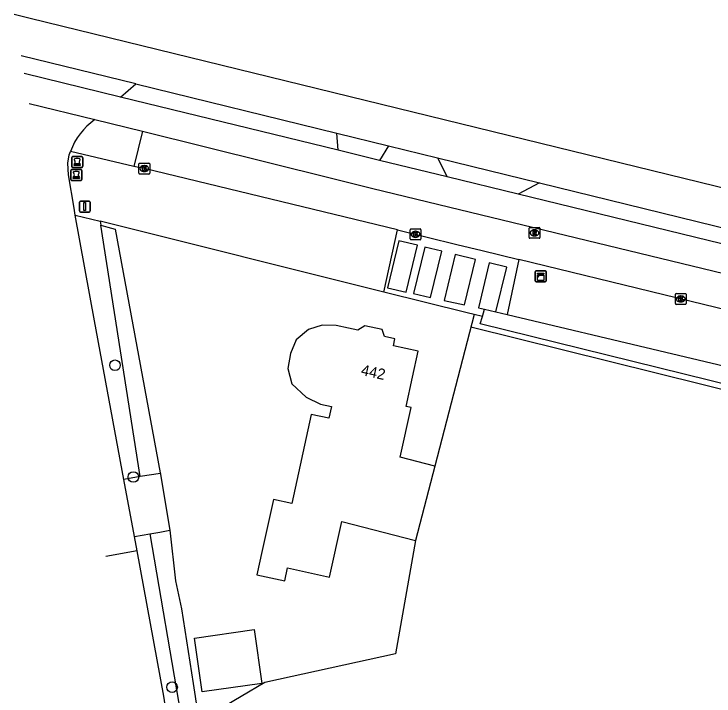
# Model space of a CAD drawing. Extents: x 163863 to 164644, y 379566 to 382155.
# Drawn here: x 164350.9 to 164415.3, y 382091.7 to 382154.5 of the extents above; entities that cross this region are included whole.
import ezdxf

# ---------------------------------------------------------------- set-up
doc = ezdxf.new("R2010")
doc.units = 0
for name, color, linetype in [('IMGEO_Berm_groen', 7, 'Continuous'), ('IMGEO_Bolder', 7, 'Continuous'), ('IMGEO_Boom', 7, 'Continuous'), ('IMGEO_Fietspad_gesloten', 7, 'Continuous'), ('IMGEO_Fietspad_open', 7, 'Continuous'), ('IMGEO_Grasland_agrarisch', 7, 'Continuous'), ('IMGEO_Groenvoorziening', 7, 'Continuous'), ('IMGEO_Hek', 7, 'Continuous'), ('IMGEO_Kast', 7, 'Continuous'), ('IMGEO_Kolk', 7, 'Continuous'), ('IMGEO_Pand', 7, 'Continuous'), ('IMGEO_Pand_nummerreeks', 7, 'Continuous'), ('IMGEO_Parkeervlak_open', 7, 'Continuous'), ('IMGEO_Rijbaan_lokaal_halfverhard', 7, 'Continuous'), ('IMGEO_Rijbaan_lokaal_open', 7, 'Continuous'), ('IMGEO_Rijbaan_regionaal_gesloten', 7, 'Continuous'), ('IMGEO_Rioolput', 7, 'Continuous'), ('IMGEO_Verkeersbordpaal', 7, 'Continuous'), ('IMGEO_Voetpad_open', 7, 'Continuous'), ('IMGEO_Waterloop', 7, 'Continuous')]:
    doc.layers.add(name, color=color, linetype=linetype)

msp = doc.modelspace()

# ---------------------------------------------------------------- linework, layer by layer
at = {"layer": 'IMGEO_Berm_groen'}
for points in [[(164356.507, 382135.999), (164358.788, 382135.429)], [(164384.91, 382128.907), (164358.788, 382135.429)]]:
    msp.add_lwpolyline(points, dxfattribs=at)
at = {"layer": 'IMGEO_Bolder'}
for p, q in [((164356.185, 382140.455), (164356.185, 382141.296)), ((164356.185, 382141.296), (164356.185, 382140.455)), ((164356.26, 382141.38), (164357.101, 382141.38)), ((164357.101, 382141.38), (164356.26, 382141.38)), ((164357.185, 382141.305), (164357.185, 382140.464)), ((164357.185, 382140.464), (164357.185, 382141.305)), ((164357.11, 382140.38), (164356.269, 382140.38)), ((164356.269, 382140.38), (164357.11, 382140.38)), ((164356.968, 382140.71), (164356.393, 382140.71)), ((164356.103, 382139.268), (164356.103, 382140.109)), ((164356.103, 382140.109), (164356.103, 382139.268)), ((164356.178, 382140.193), (164357.019, 382140.193)), ((164357.019, 382140.193), (164356.178, 382140.193)), ((164357.103, 382140.118), (164357.103, 382139.277)), ((164357.103, 382139.277), (164357.103, 382140.118)), ((164357.028, 382139.193), (164356.187, 382139.193)), ((164356.187, 382139.193), (164357.028, 382139.193)), ((164356.886, 382139.523), (164356.311, 382139.523))]:
    msp.add_line(p, q, dxfattribs=at)
for points in [[(164356.393, 382140.66), (164356.968, 382140.66), (164356.968, 382140.558), (164356.393, 382140.558), (164356.393, 382140.66)], [(164356.311, 382139.473), (164356.886, 382139.473), (164356.886, 382139.371), (164356.311, 382139.371), (164356.311, 382139.473)]]:
    msp.add_lwpolyline(points, dxfattribs=at)
for centre, radius, start, end in [((164356.263, 382141.302), 0.0779, 92.4484, 184.28452), ((164356.263, 382141.302), 0.0779, 92.4484, 184.28452), ((164356.334, 382140.871), 0.172, 289.86634, 37.64837), ((164356.449, 382141.122), 0.0482, 119.11853, 182.6026), ((164356.479, 382141.121), 0.0781, 181.25999, 199.25687), ((164356.687, 382141.192), 0.297, 198.84879, 209.67889), ((164356.513, 382141.021), 0.168, 102.85353, 121.35376), ((164357.271, 382141.509), 0.962, 208.90947, 213.66044), ((164356.68, 382140.155), 1.049, 78.76924, 101.23076), ((164357.027, 382140.871), 0.172, 142.35163, 250.13366), ((164356.847, 382141.021), 0.168, 58.64624, 77.14647), ((164356.09, 382141.509), 0.962, 326.33956, 331.09053), ((164356.674, 382141.192), 0.297, 330.32111, 341.15121), ((164356.911, 382141.122), 0.0482, 357.3974, 60.88147), ((164356.881, 382141.121), 0.0781, 340.74313, 358.74001), ((164357.107, 382141.302), 0.0779, 2.4484, 94.28452), ((164357.107, 382141.302), 0.0779, 2.4484, 94.28452), ((164356.263, 382140.458), 0.0779, 182.4484, 274.28452), ((164356.263, 382140.458), 0.0779, 182.4484, 274.28452), ((164357.107, 382140.458), 0.0779, 272.4484, 4.28452), ((164357.107, 382140.458), 0.0779, 272.4484, 4.28452), ((164356.181, 382140.115), 0.0779, 92.4484, 184.28452), ((164356.181, 382140.115), 0.0779, 92.4484, 184.28452), ((164356.252, 382139.684), 0.172, 289.86634, 37.64837), ((164356.367, 382139.935), 0.0482, 119.11853, 182.6026), ((164356.397, 382139.934), 0.0781, 181.25999, 199.25687), ((164356.605, 382140.005), 0.297, 198.84879, 209.67889), ((164356.431, 382139.834), 0.168, 102.85353, 121.35376), ((164357.189, 382140.322), 0.962, 208.90947, 213.66044), ((164356.598, 382138.968), 1.049, 78.76924, 101.23076), ((164356.945, 382139.684), 0.172, 142.35163, 250.13366), ((164356.765, 382139.834), 0.168, 58.64624, 77.14647), ((164356.008, 382140.322), 0.962, 326.33956, 331.09053), ((164356.592, 382140.005), 0.297, 330.32111, 341.15121), ((164356.829, 382139.935), 0.0482, 357.3974, 60.88147), ((164356.799, 382139.934), 0.0781, 340.74313, 358.74001), ((164357.025, 382140.115), 0.0779, 2.4484, 94.28452), ((164357.025, 382140.115), 0.0779, 2.4484, 94.28452), ((164356.181, 382139.271), 0.0779, 182.4484, 274.28452), ((164356.181, 382139.271), 0.0779, 182.4484, 274.28452), ((164357.025, 382139.271), 0.0779, 272.4484, 4.28452), ((164357.025, 382139.271), 0.0779, 272.4484, 4.28452)]:
    msp.add_arc(centre, radius, start, end, dxfattribs=at)
at = {"layer": 'IMGEO_Boom'}
for centre in [(164360.159, 382122.182), (164361.852, 382111.898), (164365.415, 382092.55)]:
    msp.add_circle(centre, 0.489, dxfattribs=at)
at = {"layer": 'IMGEO_Fietspad_gesloten'}
for points in [[(164360.676, 382146.852), (164351.794, 382149.021)], [(164380.701, 382141.967), (164360.676, 382146.852)], [(164358.291, 382144.799), (164362.677, 382143.726)], [(164362.677, 382143.726), (164380.086, 382139.395), (164383.897, 382138.464), (164391.868, 382136.525), (164462.951, 382119.296)], [(164384.514, 382141.037), (164380.701, 382141.967)], [(164390.718, 382139.524), (164384.514, 382141.037)], [(164397.276, 382137.925), (164390.718, 382139.524)], [(164432.227, 382129.4), (164397.276, 382137.925)]]:
    msp.add_lwpolyline(points, dxfattribs=at)
at = {"layer": 'IMGEO_Fietspad_open'}
msp.add_lwpolyline([(164360.676, 382146.852), (164362.069, 382148.073)], dxfattribs=at)
at = {"layer": 'IMGEO_Grasland_agrarisch'}
for points in [[(164393.22, 382126.843), (164389.6, 382112.906)], [(164387.831, 382106.038), (164385.986, 382095.611), (164373.957, 382092.98), (164369.59, 382090.415)]]:
    msp.add_lwpolyline(points, dxfattribs=at)
at = {"layer": 'IMGEO_Groenvoorziening'}
msp.add_lwpolyline([(164358.788, 382135.429), (164358.85, 382135.065)], dxfattribs=at)
at = {"layer": 'IMGEO_Hek'}
msp.add_lwpolyline([(164392.898, 382125.718), (164435.546, 382115.127)], dxfattribs=at)
at = {"layer": 'IMGEO_Kast'}
for p, q in [((164398.837, 382129.946), (164398.837, 382130.787)), ((164398.837, 382130.787), (164398.837, 382129.946)), ((164398.912, 382130.871), (164399.753, 382130.871)), ((164399.753, 382130.871), (164398.912, 382130.871)), ((164399.837, 382130.796), (164399.837, 382129.955)), ((164399.837, 382129.955), (164399.837, 382130.796)), ((164399.762, 382129.871), (164398.921, 382129.871)), ((164398.921, 382129.871), (164399.762, 382129.871))]:
    msp.add_line(p, q, dxfattribs=at)
for points in [[(164399.032, 382130.661), (164399.632, 382130.661), (164399.632, 382130.576), (164399.032, 382130.576), (164399.032, 382130.661)], [(164399.032, 382130.486), (164399.632, 382130.486), (164399.632, 382129.997), (164399.032, 382129.997), (164399.032, 382130.486)]]:
    msp.add_lwpolyline(points, dxfattribs=at)
msp.add_circle((164399.116, 382130.335), 0.0377, dxfattribs=at)
for centre, start, end in [((164398.915, 382130.793), 92.4484, 184.28452), ((164398.915, 382130.793), 92.4484, 184.28452), ((164399.759, 382130.793), 2.4484, 94.28452), ((164399.759, 382130.793), 2.4484, 94.28452), ((164398.915, 382129.949), 182.4484, 274.28452), ((164398.915, 382129.949), 182.4484, 274.28452), ((164399.759, 382129.949), 272.4484, 4.28452), ((164399.759, 382129.949), 272.4484, 4.28452)]:
    msp.add_arc(centre, 0.0779, start, end, dxfattribs=at)
at = {"layer": 'IMGEO_Kolk'}
for p, q in [((164362.356, 382139.854), (164362.356, 382140.706)), ((164362.431, 382140.78), (164363.283, 382140.78)), ((164362.844, 382140.56), (164362.869, 382140.56)), ((164363.357, 382140.706), (164363.357, 382139.854)), ((164363.283, 382139.78), (164362.431, 382139.78)), ((164362.867, 382140), (164362.842, 382140)), ((164387.322, 382133.804), (164387.322, 382134.656)), ((164387.397, 382134.73), (164388.249, 382134.73)), ((164387.81, 382134.51), (164387.835, 382134.51)), ((164388.323, 382134.656), (164388.323, 382133.804)), ((164387.833, 382133.95), (164387.808, 382133.95)), ((164388.249, 382133.73), (164387.397, 382133.73)), ((164411.735, 382127.858), (164411.735, 382128.71)), ((164411.81, 382128.784), (164412.662, 382128.784)), ((164412.736, 382128.71), (164412.736, 382127.858)), ((164412.223, 382128.564), (164412.248, 382128.564)), ((164412.662, 382127.784), (164411.81, 382127.784)), ((164412.246, 382128.004), (164412.221, 382128.004))]:
    msp.add_line(p, q, dxfattribs=at)
for points in [[(164362.356, 382139.854), (164362.356, 382140.706)], [(164362.431, 382140.78), (164363.283, 382140.78)], [(164362.677, 382140.48), (164362.8, 382140.48), (164362.8, 382140.329), (164362.93, 382140.48), (164363.094, 382140.48), (164362.948, 382140.329), (164363.101, 382140.08), (164362.949, 382140.08), (164362.864, 382140.244), (164362.8, 382140.177), (164362.8, 382140.08), (164362.677, 382140.08), (164362.677, 382140.48)], [(164363.357, 382140.706), (164363.357, 382139.854)], [(164363.283, 382139.78), (164362.431, 382139.78)], [(164387.322, 382133.804), (164387.322, 382134.656)], [(164387.397, 382134.73), (164388.249, 382134.73)], [(164388.323, 382134.656), (164388.323, 382133.804)], [(164387.643, 382134.43), (164387.766, 382134.43), (164387.766, 382134.279), (164387.896, 382134.43), (164388.06, 382134.43), (164387.914, 382134.279), (164388.067, 382134.03), (164387.915, 382134.03), (164387.83, 382134.194), (164387.766, 382134.127), (164387.766, 382134.03), (164387.643, 382134.03), (164387.643, 382134.43)], [(164388.249, 382133.73), (164387.397, 382133.73)], [(164411.735, 382127.858), (164411.735, 382128.71)], [(164411.81, 382128.784), (164412.662, 382128.784)], [(164412.736, 382128.71), (164412.736, 382127.858)], [(164412.056, 382128.484), (164412.179, 382128.484), (164412.179, 382128.333), (164412.309, 382128.484), (164412.473, 382128.484), (164412.327, 382128.333), (164412.48, 382128.084), (164412.328, 382128.084), (164412.243, 382128.248), (164412.179, 382128.181), (164412.179, 382128.084), (164412.056, 382128.084), (164412.056, 382128.484)], [(164412.662, 382127.784), (164411.81, 382127.784)]]:
    msp.add_lwpolyline(points, dxfattribs=at)
for centre, start, end in [((164362.433, 382140.704), 91.55205, 178.44795), ((164362.433, 382140.704), 91.55205, 178.44795), ((164363.281, 382140.704), 1.55205, 88.44795), ((164363.281, 382140.704), 1.55205, 88.44795), ((164362.433, 382139.856), 181.55205, 268.44795), ((164362.433, 382139.856), 181.55205, 268.44795), ((164363.281, 382139.856), 271.55205, 358.44795), ((164363.281, 382139.856), 271.55205, 358.44795), ((164387.399, 382134.654), 91.55205, 178.44795), ((164387.399, 382134.654), 91.55205, 178.44795), ((164388.247, 382134.654), 1.55205, 88.44795), ((164388.247, 382134.654), 1.55205, 88.44795), ((164387.399, 382133.806), 181.55205, 268.44795), ((164387.399, 382133.806), 181.55205, 268.44795), ((164388.247, 382133.806), 271.55205, 358.44795), ((164388.247, 382133.806), 271.55205, 358.44795), ((164411.812, 382128.708), 91.55205, 178.44795), ((164411.812, 382128.708), 91.55205, 178.44795), ((164412.66, 382128.708), 1.55205, 88.44795), ((164412.66, 382128.708), 1.55205, 88.44795), ((164411.812, 382127.86), 181.55205, 268.44795), ((164411.812, 382127.86), 181.55205, 268.44795), ((164412.66, 382127.86), 271.55205, 358.44795), ((164412.66, 382127.86), 271.55205, 358.44795)]:
    msp.add_arc(centre, 0.0765, start, end, dxfattribs=at)
for centre, major_axis, ratio, start_param, end_param in [((164362.843, 382140.28), (-0.387, 0.002), 0.722429, 4.712389, 7.853982), ((164362.868, 382140.28), (-0.39, 0.002), 0.717154, 1.570796, 4.712389), ((164387.809, 382134.23), (-0.387, 0.002), 0.722429, 4.712389, 7.853982), ((164387.834, 382134.23), (-0.39, 0.002), 0.717154, 1.570796, 4.712389), ((164412.222, 382128.284), (-0.387, 0.002), 0.722429, 4.712389, 7.853982), ((164412.247, 382128.284), (-0.39, 0.002), 0.717154, 1.570796, 4.712389)]:
    msp.add_ellipse(centre, major_axis=major_axis, ratio=ratio, start_param=start_param, end_param=end_param, dxfattribs=at)
at = {"layer": 'IMGEO_Pand'}
for points in [[(164389.6, 382112.906), (164386.417, 382113.726), (164387.414, 382118.288), (164386.954, 382118.388), (164387.546, 382121.1), (164388.067, 382123.484), (164385.781, 382123.983), (164385.919, 382124.617), (164384.967, 382124.825), (164384.761, 382125.471), (164383.16, 382125.821), (164382.517, 382125.408), (164381.662, 382125.595), (164380.503, 382125.848), (164379.215, 382125.876), (164377.976, 382125.467), (164376.831, 382124.522), (164376.328, 382123.256), (164376.062, 382121.898), (164376.427, 382120.475), (164377.764, 382119.237), (164379.079, 382118.592), (164380.083, 382118.372), (164379.85, 382117.305), (164378.218, 382117.661), (164376.422, 382109.445), (164374.743, 382109.831), (164373.716, 382105.14), (164373.226, 382102.901), (164375.789, 382102.34), (164376.049, 382103.53), (164379.918, 382102.683), (164381.031, 382107.789), (164387.831, 382106.038)], [(164389.6, 382112.906), (164387.831, 382106.038)], [(164373.663, 382092.9), (164368.177, 382092.124), (164367.477, 382097.076), (164372.963, 382097.852), (164373.663, 382092.9)]]:
    msp.add_lwpolyline(points, dxfattribs=at)
at = {"layer": 'IMGEO_Parkeervlak_open'}
msp.add_lwpolyline([(164394.183, 382127.338), (164395.216, 382127.093)], dxfattribs=at)
at = {"layer": 'IMGEO_Rijbaan_lokaal_halfverhard'}
msp.add_lwpolyline([(164394.676, 381881.88), (164388.097, 381917.443), (164387.742, 381919.592), (164379.466, 381969.665), (164377.032, 381983.081), (164376.328, 381987.84), (164375.071, 382000), (164368.326, 382065.243), (164366.228, 382081.359), (164364.658, 382091.736), (164362.186, 382105.089)], dxfattribs=at)
at = {"layer": 'IMGEO_Rijbaan_lokaal_open'}
for points in [[(164352.259, 382146.273), (164358.291, 382144.799)], [(164356.507, 382135.999), (164356.39, 382136.646), (164355.877, 382139.695), (164355.811, 382140.786), (164355.948, 382141.543), (164356.054, 382141.847)], [(164360.971, 382111.652), (164358.266, 382126.263), (164356.507, 382135.999)], [(164364.335, 382112.233), (164362.476, 382111.931)], [(164364.335, 382112.233), (164364.354, 382112.133), (164365.199, 382106.995)], [(164362.476, 382111.931), (164360.971, 382111.652)], [(164361.941, 382106.41), (164360.971, 382111.652)], [(164363.361, 382106.673), (164364.28, 382106.834), (164365.199, 382106.995)], [(164361.941, 382106.41), (164363.361, 382106.673)], [(164362.186, 382105.089), (164361.941, 382106.41)], [(164362.186, 382105.089), (164359.316, 382104.565)]]:
    msp.add_lwpolyline(points, dxfattribs=at)
msp.add_arc((164362.15, 382139.551), 6.514, 126.32819, 159.36275, dxfattribs=at)
at = {"layer": 'IMGEO_Rijbaan_regionaal_gesloten'}
for points in [[(164350.865, 382154.51), (164352.346, 382154.141), (164422.808, 382136.877), (164448.236, 382130.698), (164525.74, 382111.863), (164595.632, 382094.807)], [(164362.069, 382148.073), (164351.518, 382150.649)], [(164362.069, 382148.073), (164380.564, 382143.542)], [(164380.564, 382143.542), (164385.347, 382142.37)], [(164385.347, 382142.37), (164389.853, 382141.266)], [(164389.853, 382141.266), (164399.244, 382138.965)], [(164399.244, 382138.965), (164431.396, 382131.087)]]:
    msp.add_lwpolyline(points, dxfattribs=at)
at = {"layer": 'IMGEO_Rioolput'}
for p, q in [((164398.268, 382133.94), (164398.268, 382134.792)), ((164398.343, 382134.866), (164399.195, 382134.866)), ((164398.756, 382134.646), (164398.781, 382134.646)), ((164399.269, 382134.792), (164399.269, 382133.94)), ((164399.195, 382133.866), (164398.343, 382133.866)), ((164398.779, 382134.086), (164398.754, 382134.086))]:
    msp.add_line(p, q, dxfattribs=at)
for points in [[(164398.268, 382133.94), (164398.268, 382134.792)], [(164398.343, 382134.866), (164399.195, 382134.866)], [(164398.857, 382134.564), (164398.605, 382134.566), (164398.605, 382134.166)], [(164399.269, 382134.792), (164399.269, 382133.94)], [(164399.195, 382133.866), (164398.343, 382133.866)], [(164398.605, 382134.166), (164398.729, 382134.166), (164398.729, 382134.328), (164398.74, 382134.328)], [(164398.783, 382134.485), (164398.729, 382134.485), (164398.729, 382134.404)], [(164398.729, 382134.404), (164398.781, 382134.404)], [(164398.787, 382134.299), (164398.858, 382134.166), (164398.998, 382134.166), (164398.933, 382134.292)]]:
    msp.add_lwpolyline(points, dxfattribs=at)
for centre, radius, start, end in [((164398.345, 382134.79), 0.0765, 91.55205, 178.44795), ((164398.345, 382134.79), 0.0765, 91.55205, 178.44795), ((164398.856, 382134.454), 0.109, 350.36119, 89.41601), ((164399.193, 382134.79), 0.0765, 1.55205, 88.44795), ((164399.193, 382134.79), 0.0765, 1.55205, 88.44795), ((164398.345, 382133.942), 0.0765, 181.55205, 268.44795), ((164398.345, 382133.942), 0.0765, 181.55205, 268.44795), ((164398.739, 382134.275), 0.0533, 26.02933, 88.69889), ((164398.765, 382134.593), 0.19, 274.7715, 282.96867), ((164398.789, 382134.389), 0.0964, 77.00612, 93.18647), ((164398.803, 382134.446), 0.0378, 276.66336, 79.67722), ((164398.854, 382134.454), 0.112, 277.58423, 350.98172), ((164398.838, 382134.239), 0.108, 29.51342, 73.79051), ((164399.193, 382133.942), 0.0765, 271.55205, 358.44795), ((164399.193, 382133.942), 0.0765, 271.55205, 358.44795)]:
    msp.add_arc(centre, radius, start, end, dxfattribs=at)
for centre, major_axis, ratio, start_param, end_param in [((164398.755, 382134.366), (-0.387, 0.002), 0.722429, 4.712389, 7.853982), ((164398.78, 382134.366), (-0.39, 0.002), 0.717154, 1.570796, 4.712389)]:
    msp.add_ellipse(centre, major_axis=major_axis, ratio=ratio, start_param=start_param, end_param=end_param, dxfattribs=at)
at = {"layer": 'IMGEO_Verkeersbordpaal'}
for p, q in [((164356.886, 382136.385), (164356.886, 382137.185)), ((164356.886, 382137.185), (164356.886, 382136.385)), ((164356.986, 382137.285), (164357.776, 382137.285)), ((164357.776, 382137.285), (164356.986, 382137.285)), ((164357.876, 382137.185), (164357.876, 382136.385)), ((164357.876, 382136.385), (164357.876, 382137.185)), ((164357.776, 382136.285), (164356.986, 382136.285)), ((164356.986, 382136.285), (164357.776, 382136.285))]:
    msp.add_line(p, q, dxfattribs=at)
msp.add_lwpolyline([(164357.306, 382137.16), (164357.456, 382137.16), (164357.456, 382136.41), (164357.306, 382136.41), (164357.306, 382137.16)], dxfattribs=at)
for centre, start, end in [((164356.986, 382137.185), 90, 180), ((164356.986, 382137.185), 90, 180), ((164357.776, 382137.185), 0, 90), ((164357.776, 382137.185), 360, 90), ((164356.986, 382136.385), 180, 270), ((164356.986, 382136.385), 180, 270), ((164357.776, 382136.385), 270, 0), ((164357.776, 382136.385), 270, 0)]:
    msp.add_arc(centre, 0.1, start, end, dxfattribs=at)
at = {"layer": 'IMGEO_Voetpad_open'}
for points in [[(164362.677, 382143.726), (164361.904, 382140.469)], [(164380.701, 382141.967), (164380.564, 382143.542)], [(164385.347, 382142.37), (164384.514, 382141.037)], [(164361.904, 382140.469), (164356.054, 382141.847)], [(164389.853, 382141.266), (164390.718, 382139.524)], [(164386.164, 382134.631), (164362.857, 382140.279), (164361.904, 382140.469)], [(164399.244, 382138.965), (164397.276, 382137.925)], [(164384.91, 382128.907), (164386.164, 382134.631)], [(164386.164, 382134.631), (164391.611, 382133.307), (164393.95, 382132.737), (164397.339, 382131.912)], [(164388, 382133.219), (164386.284, 382133.637), (164385.229, 382129.3), (164386.956, 382128.921), (164388, 382133.219)], [(164390.231, 382132.676), (164388.663, 382133.057), (164387.622, 382128.775), (164389.199, 382128.43), (164390.231, 382132.676)], [(164393.353, 382131.916), (164391.481, 382132.371), (164390.454, 382128.155), (164392.336, 382127.743), (164393.353, 382131.916)], [(164395.216, 382127.093), (164396.221, 382131.218), (164394.612, 382131.609), (164393.603, 382127.465), (164394.183, 382127.338)], [(164397.339, 382131.912), (164396.25, 382126.848)], [(164437.356, 382122.165), (164397.339, 382131.912)], [(164393.22, 382126.843), (164392.563, 382126.997), (164384.91, 382128.907)], [(164393.977, 382126.658), (164393.22, 382126.843)], [(164393.977, 382126.658), (164394.183, 382127.338)], [(164395.216, 382127.093), (164396.25, 382126.848)]]:
    msp.add_lwpolyline(points, dxfattribs=at)
at = {"layer": 'IMGEO_Waterloop'}
for points in [[(164362.476, 382111.931), (164358.85, 382135.065)], [(164358.85, 382135.065), (164359.516, 382134.882), (164360.183, 382134.698), (164364.328, 382112.273), (164364.335, 382112.233)], [(164396.25, 382126.848), (164438.135, 382116.921), (164437.949, 382115.908)], [(164435.113, 382110.541), (164435.91, 382115.587), (164393.78, 382126.007), (164393.977, 382126.658)], [(164365.199, 382106.995), (164365.725, 382102.336), (164366.273, 382099.763), (164367.356, 382092.892), (164367.768, 382090.275)], [(164363.361, 382106.673), (164366.209, 382089.978), (164367.499, 382080), (164369.311, 382067.964), (164371.068, 382052.247), (164373.556, 382027.013), (164374.125, 382027.073), (164374.694, 382027.134)]]:
    msp.add_lwpolyline(points, dxfattribs=at)

# ---------------------------------------------------------------- texts
at = {"layer": 'IMGEO_Pand_nummerreeks'}
msp.add_text('442', height=1, rotation=347.6986, dxfattribs=at).set_placement((164382.742, 382121.29))

doc.saveas('drawing.dxf')
